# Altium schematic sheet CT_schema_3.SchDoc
size 218 x 258 mm
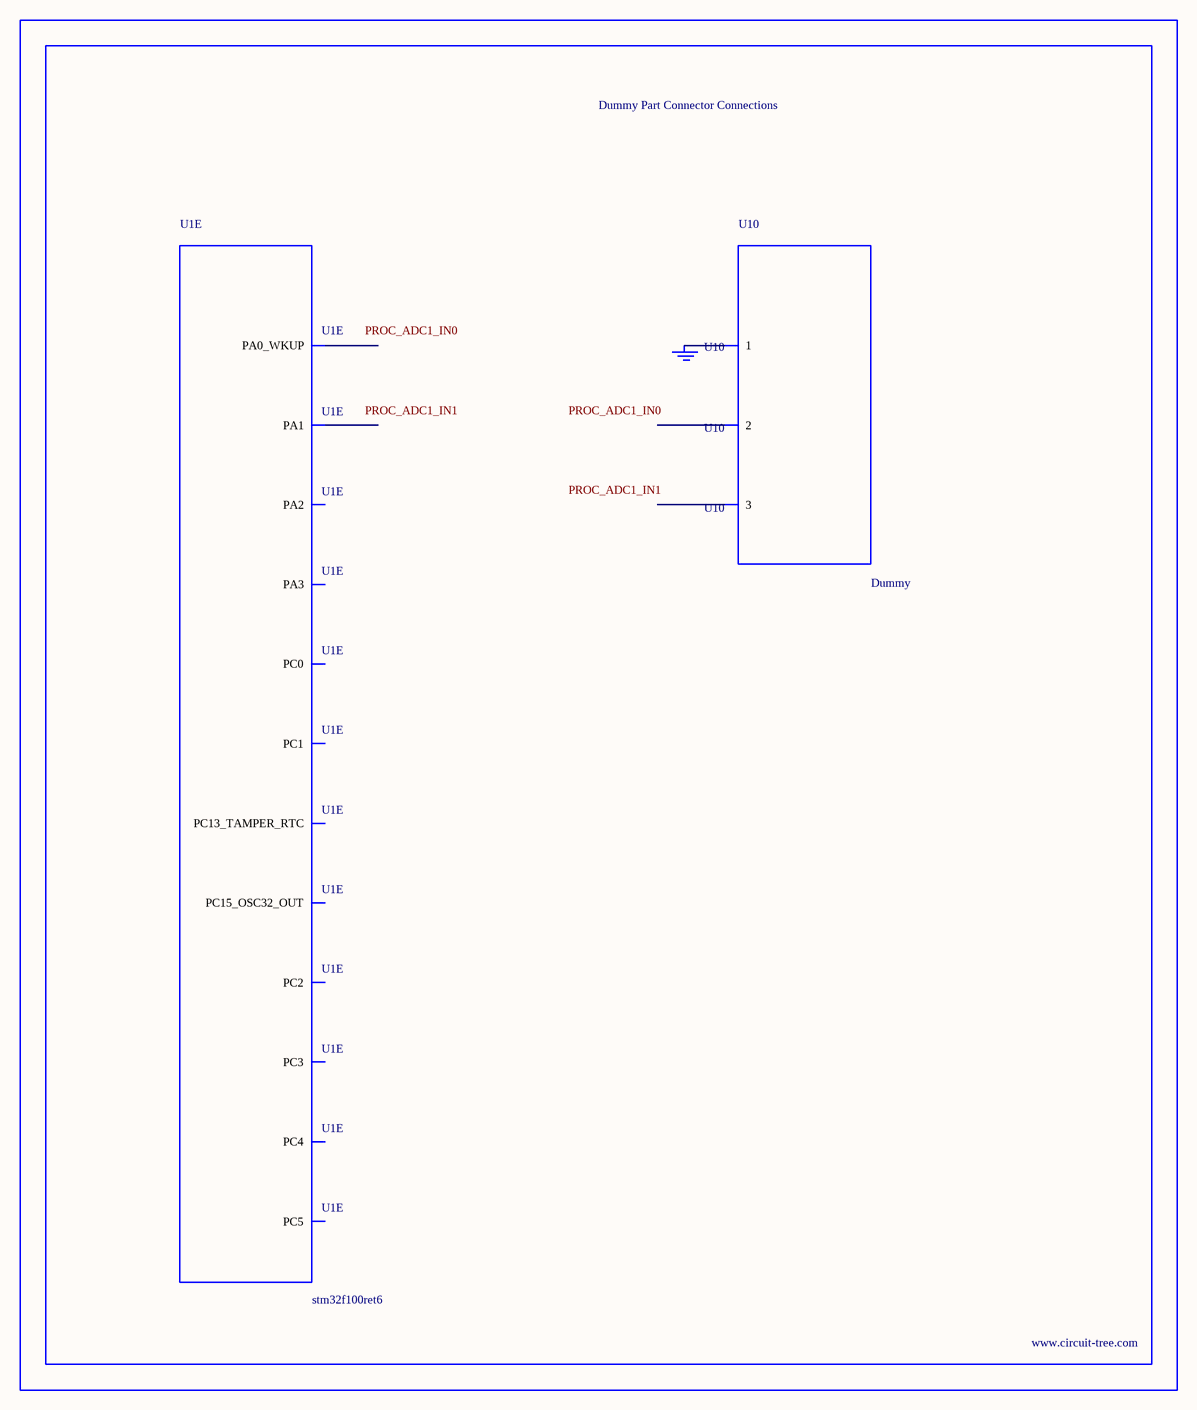
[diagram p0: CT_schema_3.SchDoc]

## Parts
BORDER2  (no value)
GND_INSTANCE_2_0  (no value)
U1  stm32f100ret6  [LQFP64]  (part E of 5)
U10  Dummy  [DUMMY_PACKAGE_96]

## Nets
NetGND_INSTANCE_2_0_0: GND_INSTANCE_2_0.0(GND) U10.1

Not connected (* = marked no-connect by the designer): U1 2(PC13_TAMPER_RTC) 4(PC15_OSC32_OUT) 8(PC0) 9(PC1) 10(PC2) 11(PC3) 14(PA0_WKUP) 15(PA1) 16(PA2) 17(PA3) 24(PC4) 25(PC5); U10 2 3

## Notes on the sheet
- Labels drawn without touching a wire or pin: PROC_ADC1_IN0, PROC_ADC1_IN1

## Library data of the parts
BORDER2 = BORDER_PAGE2
GND_INSTANCE_2_0 = GND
